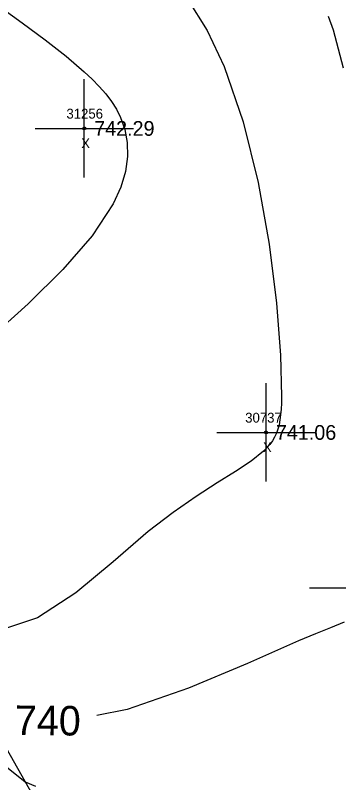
# Model space of a CAD drawing. Extents: x 1376587 to 1378239, y 1000335 to 1003031.
# Drawn here: x 1377122.4 to 1377155.3, y 1002132.5 to 1002210.4 of the extents above; entities that cross this region are included whole.
import ezdxf

# ---------------------------------------------------------------- set-up
doc = ezdxf.new("R2010")
doc.units = 0
for name, color, linetype in [('RD_DTM_BkLn2', 7, 'Continuous'), ('RD_DTM_Major1', 7, 'Continuous'), ('RD_DTM_Major1_Lbl', 7, 'Continuous'), ('RD_DTM_Minor1', 7, 'Continuous'), ('RD_EX_Misc', 7, 'Continuous'), ('RD_EX_Misc_txCode', 7, 'Continuous'), ('RD_EX_TX_Misc_ELEV', 7, 'Continuous'), ('RD_SMD_Locator', 7, 'Continuous')]:
    doc.layers.add(name, color=color, linetype=linetype)

msp = doc.modelspace()

# ---------------------------------------------------------------- linework, layer by layer
at = {"layer": 'RD_DTM_BkLn2'}
msp.add_lwpolyline([(1377334.808, 1002026.055), (1377284.229, 1002013.339), (1377249.257, 1001988.727), (1377213.659, 1001973.589), (1377188.957, 1002014.33), (1377158.44, 1002070.963), (1377139.047, 1002104.941), (1377113.892, 1002149.475), (1377071.66, 1002218.399), (1377041.895, 1002260.076), (1377023.693, 1002288.088), (1377010.927, 1002302.495), (1376992.725, 1002332.02), (1376976.352, 1002351.559)], dxfattribs=at)
at = {"layer": 'RD_DTM_Major1'}
for points in [[(1377154.248, 1002210.363), (1377154.749, 1002208.984), (1377155.777, 1002205.106)], [(1377155.859, 1002148.79), (1377154.479, 1002148.229), (1377152.939, 1002147.605), (1377151.216, 1002146.886), (1377146.037, 1002144.598), (1377140.059, 1002142.075), (1377133.793, 1002139.912), (1377130.736, 1002139.302)]]:
    msp.add_lwpolyline(points, dxfattribs=at)
at = {"layer": 'RD_DTM_Minor1'}
for points in [[(1377139.953, 1002212.125), (1377141.934, 1002208.892), (1377143.663, 1002205.25), (1377145.604, 1002199.616), (1377147.116, 1002193.458), (1377148.231, 1002187.184), (1377148.978, 1002181.197), (1377149.389, 1002175.903), (1377149.493, 1002171.707), (1377149.479, 1002171.035), (1377149.452, 1002170.419), (1377149.407, 1002169.854), (1377149.342, 1002169.334), (1377149.253, 1002168.856), (1377149.139, 1002168.414), (1377148.986, 1002167.983), (1377148.799, 1002167.582), (1377148.576, 1002167.205), (1377148.313, 1002166.846), (1377148.01, 1002166.499), (1377147.665, 1002166.158), (1377146.417, 1002165.165), (1377144.833, 1002164.113), (1377142.955, 1002162.936), (1377140.823, 1002161.57), (1377138.477, 1002159.948), (1377135.958, 1002158.007), (1377132.371, 1002154.92), (1377128.598, 1002151.781), (1377124.688, 1002149.229), (1377120.693, 1002147.905)], [(1377120.539, 1002211.541), (1377123.12, 1002209.697), (1377125.48, 1002207.946), (1377127.591, 1002206.287), (1377129.428, 1002204.715), (1377130.24, 1002203.954), (1377130.975, 1002203.204), (1377131.632, 1002202.452), (1377132.209, 1002201.687), (1377132.707, 1002200.899), (1377133.123, 1002200.075), (1377133.565, 1002198.844), (1377133.818, 1002197.52), (1377133.855, 1002196.104), (1377133.648, 1002194.595), (1377133.171, 1002192.994), (1377132.395, 1002191.3), (1377130.234, 1002188.044), (1377127.266, 1002184.61), (1377123.734, 1002181.12), (1377119.883, 1002177.696)], [(1377121.547, 1002134.087), (1377123.438, 1002132.574), (1377124.48, 1002132.12)]]:
    msp.add_lwpolyline(points, dxfattribs=at)
at = {"layer": 'RD_EX_Misc'}
for p, q in [((1377129.453, 1002193.953), (1377129.453, 1002203.953)), ((1377124.453, 1002198.953), (1377134.453, 1002198.953)), ((1377147.923, 1002163.069), (1377147.923, 1002173.069)), ((1377142.923, 1002168.069), (1377152.923, 1002168.069)), ((1377152.345, 1002152.297), (1377162.345, 1002152.297))]:
    msp.add_line(p, q, dxfattribs=at)
at = {"layer": 'RD_SMD_Locator'}
for centre in [(1377129.453, 1002198.953), (1377147.923, 1002168.069)]:
    msp.add_circle(centre, 0.15, dxfattribs=at)

# ---------------------------------------------------------------- texts
at = {"layer": 'RD_DTM_Major1_Lbl'}
msp.add_text('740', height=3, rotation=359.4925, dxfattribs=at).set_placement((1377122.388, 1002137.334))
at = {"layer": 'RD_EX_Misc_txCode'}
for s, p in [('31256', (1377127.634, 1002199.953)), ('X', (1377129.138, 1002196.953)), ('30737', (1377145.805, 1002169.069)), ('X', (1377147.608, 1002166.069))]:
    msp.add_text(s, height=1, dxfattribs=at).set_placement(p)
at = {"layer": 'RD_EX_TX_Misc_ELEV'}
for s, p in [('742.29', (1377130.453, 1002198.203)), ('741.06', (1377148.923, 1002167.319))]:
    msp.add_text(s, height=1.5, dxfattribs=at).set_placement(p)

doc.saveas('drawing.dxf')
